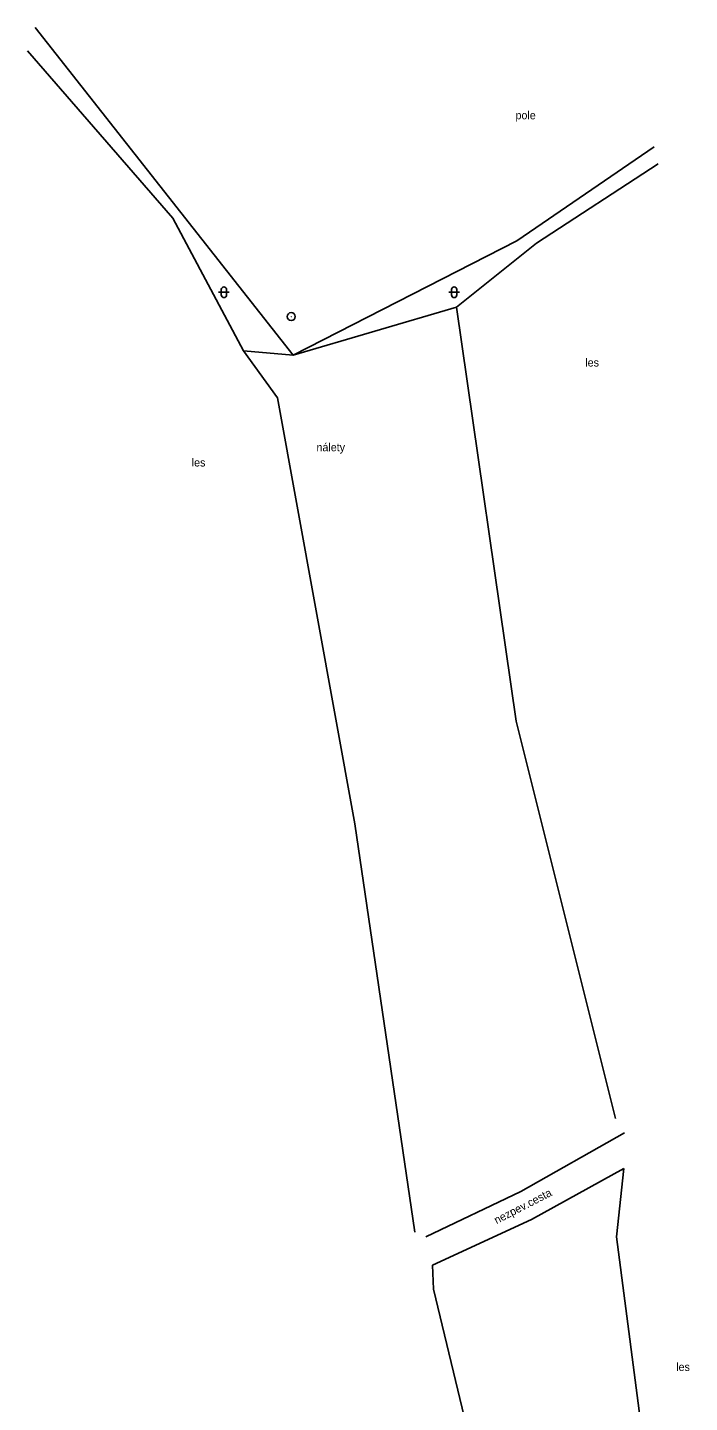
# Model space of a CAD drawing. Extents: x -762483 to -761175, y -1154655 to -1152452.
# Drawn here: x -761573.1 to -761511, y -1153451.6 to -1153322.7 of the extents above; entities that cross this region are included whole.
import ezdxf

# ---------------------------------------------------------------- set-up
doc = ezdxf.new("R2010")
doc.units = 0
for name, color, linetype in [('MAP_ZN_BP', 7, 'Continuous'), ('POMOC_POPIS', 7, 'Continuous'), ('ROZHRANÍ_PLOCH', 7, 'Continuous'), ('ZELEŇ', 7, 'Continuous'), ('ZN_KULTUR', 7, 'Continuous')]:
    doc.layers.add(name, color=color, linetype=linetype)

msp = doc.modelspace()

# ---------------------------------------------------------------- linework, layer by layer
at = {"layer": 'MAP_ZN_BP'}
for radius in [0.375, 0.0005]:
    msp.add_circle((-761548.35, -1153349.8), radius, dxfattribs=at)
at = {"layer": 'ROZHRANÍ_PLOCH'}
for points in [[(-761535.74, -1153436.06), (-761526.82, -1153431.82), (-761517.13, -1153426.3)], [(-761535.12, -1153438.71), (-761525.84, -1153434.44), (-761517.18, -1153429.66)]]:
    msp.add_lwpolyline(points, dxfattribs=at)
at = {"layer": 'ZELEŇ'}
for points in [[(-761572.35, -1153322.7), (-761548.18, -1153353.43), (-761527.2, -1153342.71), (-761514.32, -1153333.89)], [(-761552.83, -1153353), (-761559.44, -1153340.58), (-761573.06, -1153324.89)], [(-761532.86, -1153348.91), (-761525.36, -1153342.93), (-761513.95, -1153335.49)], [(-761552.83, -1153353), (-761548.18, -1153353.43), (-761532.86, -1153348.91)], [(-761517.96, -1153424.96), (-761527.27, -1153387.73), (-761532.86, -1153348.91)], [(-761536.76, -1153435.61), (-761542.4, -1153397.36), (-761549.63, -1153357.41), (-761552.83, -1153353)], [(-761512.13, -1153474.66), (-761514.45, -1153462.2), (-761517.85, -1153436.07), (-761517.18, -1153429.66)], [(-761522.41, -1153530.52), (-761521.16, -1153516.7), (-761525.36, -1153498.92), (-761526.95, -1153474.42), (-761535, -1153440.98), (-761535.12, -1153438.71)]]:
    msp.add_lwpolyline(points, dxfattribs=at)
at = {"layer": 'ZN_KULTUR'}
for p, q in [((-761555.15, -1153347.52), (-761554.15, -1153347.52)), ((-761554.9, -1153347.77), (-761554.9, -1153347.27)), ((-761554.4, -1153347.77), (-761554.4, -1153347.27)), ((-761533.58, -1153347.52), (-761532.58, -1153347.52)), ((-761533.33, -1153347.77), (-761533.33, -1153347.27)), ((-761532.83, -1153347.77), (-761532.83, -1153347.27))]:
    msp.add_line(p, q, dxfattribs=at)
for centre, start, end in [((-761554.65, -1153347.27), 0, 180), ((-761554.65, -1153347.77), 180, 360), ((-761533.08, -1153347.27), 0, 180), ((-761533.08, -1153347.77), 180, 360)]:
    msp.add_arc(centre, 0.25, start, end, dxfattribs=at)

# ---------------------------------------------------------------- texts
at = {"layer": 'POMOC_POPIS'}
msp.add_text('nezpev.cesta', height=0.75, rotation=27.3399, dxfattribs=at).set_placement((-761529.1, -1153434.88))
at = {"layer": 'ZELEŇ'}
for s, p in [('pole', (-761527.33, -1153331.3)), ('les', (-761520.79, -1153354.48)), ('nálety', (-761545.98, -1153362.42)), ('les', (-761557.67, -1153363.85)), ('les', (-761512.27, -1153448.63))]:
    msp.add_text(s, height=0.75, dxfattribs=at).set_placement(p)

doc.saveas('drawing.dxf')
